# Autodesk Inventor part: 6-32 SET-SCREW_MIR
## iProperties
Created: 2007-08
Part Number: 6-32 SET-SCREW_MIR
Document SubType Name: Modeling
Mass: 0.0379541 g
Surface Area: 1.01226 cm^2
Volume: 0.0379541 cm^3
Density: 1 g/cm^3
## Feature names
1. Derived Body1 [Tagging]
